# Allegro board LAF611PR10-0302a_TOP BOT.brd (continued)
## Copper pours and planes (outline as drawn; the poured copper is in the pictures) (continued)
LX_3V on BOTTOM (solid shape): 208.01,53.29 209.23,53.29 209.35,53.18 209.35,51.66 209.37,51.64 209.37,51.63 209.45,51.51 209.57,51.43 209.58,51.43 209.94,51.07 210.17,51.07 210.21,51.03 212.29,51.03 212.36,51.1 213.18,51.1 213.25,51.03 213.25,50.86 213.21,50.82 212.39,50.82 212.34,50.77 210.63,50.77 210.22,50.37 209.06,50.37 208.96,50.47 208.61,50.47 208.5,50.36 206.9,50.36 205.66,51.6 203.01,51.6 202.94,51.67 202.94,53.98 203,54.04 207.26,54.04
LX_5V on TOP (solid shape): 123.18,50.74 123.18,49.24 123.1,49.16 121.47,49.16 121.43,49.19 121.43,50.47 121.88,50.91 123.01,50.91
LX_5V on BOTTOM (solid shape): 125.13,53.61 125.13,52.74 124.93,52.55 124.93,52.01 124.37,51.44 124.37,50.71 124.33,50.7 124.19,50.6 124.11,50.43 124.11,50.42 123.56,49.87 123.56,46.75 123.5,46.69 121.13,46.69 121.06,46.76 121.06,50.51 120.28,51.29 120.28,52.07 120.42,52.21 123.65,52.21 124.35,52.91 124.35,53.56 124.49,53.7 125.04,53.7
LX_+1.05V on TOP (solid shape): 140.69,47.28 140.69,46.92 140.5,46.73 139.08,46.73 138.84,46.97 138.84,47.43 139.03,47.63 140.34,47.63
LX_+1.05V on TOP (solid shape): 135.45,46 135.45,44.36 135.36,44.27 134.85,44.27 134.78,44.3 134.75,44.37 134.72,44.51 134.63,44.63 134.63,45.98 134.79,46.13 135.32,46.13
LX_+1.05V on BOTTOM (solid shape): 142.79,51.73 142.79,48.32 142.64,48.17 142.22,48.17 141.21,47.16 141.21,45 141.16,44.95 139.54,44.95 139.48,45.01 139.48,48.16 139.3,48.33 134.9,48.33 134.77,48.46 134.77,51.07 134.89,51.18 139.82,51.18 140.16,51.51 140.16,51.69 140.35,51.88 142.64,51.88
LX_+1.05V on BOTTOM (solid shape): 135.33,45.26 136.15,45.26 136.2,45.22 136.2,44.34 136.16,44.31 135.89,44.31 135.83,44.25 135.58,44.01 135.58,43.99 135.58,43.5 135.51,43.43 135.51,42.67 135.43,42.59 135.28,42.59 135.2,42.67 135.2,43.61 135.2,43.9 134.83,44.27 134.83,45.23 134.99,45.39 135.2,45.39
LX_VCCIO on BOTTOM (solid shape): 52.12,121.6 52.29,121.43 52.29,119.5 52.41,119.38 53.73,119.38 53.85,119.26 53.84,119.24 53.84,117.35 53.17,116.68 51.04,116.68 50.52,116.16 50.52,114.45 50.72,114.25 50.72,113.51 50.56,113.35 49.68,113.35 49.57,113.47 49.57,115.37 48.88,116.06 46.93,116.06 45.83,116.06 45.83,116.22 45.91,116.29 48.55,116.29 48.98,116.72 49.98,116.72 51.23,117.98 51.23,119.43 50.93,119.73 50.93,121.4 51.13,121.61 52.12,121.61
MCT on TOP (solid shape): 18.45,83.09 18.45,75.71 18.85,75.3 18.85,73.27 18.45,72.86 18.45,68.18 18.31,68.04 17.44,68.04 17.3,68.18 17.3,73.39 17.75,73.84 17.75,75.04 17.3,75.49 17.3,83.15 17.52,83.37 18.16,83.37
MCT on BOTTOM (solid shape): 19.43,83.49 19.43,81.72 19.32,81.61 17.74,81.61 17.55,81.79 17.55,83.42 17.64,83.51 19.41,83.51
MIC_CAP on TOP (solid shape): 31.5,22.27 31.5,21.7 31.44,21.64 31.14,21.64 30.86,21.36 30.86,20.3 31.07,20.1 31.07,18.47 31,18.4 30.9,18.4 30.85,18.45 30.85,19.9 30.43,20.32 30.43,22.26 30.47,22.31 31.46,22.31
NVVDD_B+ on TOP (solid shape): 223.71,67.1 223.71,65.41 223.53,65.1 223.71,64.79 223.71,63.25 222.85,62.4 221.65,62.4 221.28,62.77 221.28,67.64 221.54,67.91 222.9,67.91
NVVDD_B+ on TOP (solid shape): 234.07,67.26 234.07,65.54 234.05,65.47 233.98,65.44 233.64,65.09 233.98,64.73 234.05,64.7 234.07,64.63 234.07,62.79 233.55,62.27 233.52,62.27 233.3,62.25 233.14,62.09 231.48,62.09 231.21,62.36 231.21,67.63 231.33,67.75 233.59,67.75
NVVDD_B+ on TOP (solid shape): 214.15,67.34 214.15,65.33 214.09,65.24 213.97,65.27 213.35,65.04 213.97,64.8 214.09,64.83 214.15,64.74 214.15,62.54 213.88,62.26 211.36,62.26 211.16,62.46 211.16,64.12 210.99,64.3 210.99,67.47 211.34,67.82 213.67,67.82
NVVDD_B+ on BOTTOM (solid shape): 225.86,67.81 225.86,66.69 225.74,66.57 224.54,66.57 224.32,66.35 224.32,65.7 224.24,65.62 223.77,65.62 223.49,65.34 223.49,62.29 223.5,62.28 223.5,62.27 224.03,61.75 224.04,61.75 224.22,61.56 230.43,61.56 231.23,62.36 231.23,67.53 231.46,67.77 235.89,67.77 235.93,67.73 235.93,66.54 234.63,66.54 234.43,66.35 234.43,65.59 234.33,65.49 233.83,65.49 233.43,65.08 233.43,62.28 233.39,62.27 233.1,61.92 233.39,61.57 233.43,61.57 233.43,60.71 231.46,58.74 229.13,58.74 229.12,58.76 226,58.76 223.56,56.31 215.82,56.31 215.32,56.81 212.87,56.81 211.18,58.51 211.18,67.43 211.5,67.75 215.87,67.75 215.98,67.64 215.98,66.47 215.85,66.34 214.61,66.34 214.44,66.17 214.44,66.15 214.44,65.49 214.36,65.41 213.53,65.41 213.33,65.21 213.33,62.34 214.12,61.56 215.11,61.56 215.12,61.56 215.23,61.53 215.35,61.56 215.36,61.56 220.14,61.56 221.16,62.57 221.16,67.52 221.52,67.89 225.78,67.89
NVVDD_B+ on VCC: 234.98,62.48 234.9,62.56 218.77,62.56 217.5,63.83 212.24,63.83 212.24,67.64 234.8,67.64 234.98,67.46
PCH_AZ_CODEC_BITCLK on TOP (solid shape): 35.5,15.53 35.5,15.13 35.33,14.96 35.33,14.35 35.26,14.27 34.8,14.27 34.72,14.35 34.72,15.7 34.42,16 32.92,16 32.84,16.08 32.84,16.18 32.89,16.23 34.8,16.23
RING2 on TOP (solid shape): 17.17,14.6 17.17,12.01 17.09,11.94 16.61,11.94 16.54,12.01 16.54,14.55 16.66,14.68 17.09,14.68
RING2 on TOP (solid shape): 32.66,20.53 32.66,20.35 31.87,19.56 31.87,18.45 31.85,18.42 31.69,18.42 31.62,18.5 31.62,20.48 31.8,20.66 32.53,20.66
RING2_R on TOP (solid shape): 17.14,11.51 17.14,8.79 16.68,8.32 15.77,8.32 15.27,8.82 15.27,10.4 15.51,10.65 15.51,11.52 15.62,11.63 17.03,11.63
SA_SW on BOTTOM (solid shape): 103.42,139.01 103.42,138.24 103.37,138.2 102.1,138.2 101.95,138.05 101.95,134.27 101.87,134.19 101.1,134.19 101.1,134.18 99.88,135.4 99.88,136.57 99.72,136.73 99.63,136.73 99.63,136.73 99.52,136.75 99.41,136.73 99.4,136.73 98.39,136.73 98.39,137.63 98.36,137.66 97.63,137.66 97.59,137.62 97.59,136.76 97.56,136.73 96.6,136.73 96.54,136.78 96.54,138.88 96.69,139.02 103.41,139.02
SLEEVE on TOP (solid shape): 18.6,14.43 18.6,13.68 18.52,13.61 18.37,13.61 18.16,13.4 18.16,11.99 18.11,11.94 17.54,11.94 17.5,11.98 17.5,14.34 17.72,14.56 18.47,14.56
SLEEVE on TOP (solid shape): 32.07,21.28 32.1,21.23 32.12,21.19 32.12,20.98 31.98,20.84 31.78,20.84 31.47,20.52 31.47,18.45 31.41,18.4 31.3,18.4 31.23,18.47 31.23,20.24 31.01,20.46 31.01,21.28 31.22,21.49 31.75,21.49 31.85,21.5
SLEEVE_R on TOP (solid shape): 19.13,11.54 19.13,10.77 19.46,10.44 19.46,8.93 19.14,8.62 17.73,8.62 17.47,8.88 17.47,11.53 17.55,11.61 19.06,11.61
SNB_1.0VS_VGAP on BOTTOM (solid shape): 201.49,78.38 201.49,77.34 201.09,76.94 201.09,76.38 200.98,76.28 200.44,76.28 200.29,76.43 200.29,78.29 200.47,78.47 201.4,78.47
SNB_VCCIO on BOTTOM (solid shape): 54.45,121.47 54.53,121.44 54.61,121.44 54.7,121.44 54.79,121.47 54.98,121.47 55.11,121.34 55.11,120.89 55.19,120.81 55.64,120.81 55.74,120.71 55.74,119.73 55.66,119.65 53.69,119.65 53.55,119.79 53.55,121.41 53.62,121.47 54.44,121.47
SNUB1_CHG on TOP (solid shape): 243.8,45.02 243.8,42.48 243.73,42.4 242.9,42.4 242.75,42.56 242.75,43.56 242.49,43.81 241.99,43.81 241.81,43.99 241.81,44.98 241.92,45.1 243.73,45.1
SNUB2_CHG on TOP (solid shape): 240.93,56.28 240.93,55.08 240.67,54.83 237.63,54.83 237.44,55.02 237.44,56.22 237.66,56.44 240.77,56.44
SNUB_+1.05V on BOTTOM (solid shape): 141.34,43.43 141.34,42.44 141.18,42.29 140.7,42.29 140.36,41.95 140.36,41.45 140.21,41.3 139.58,41.3 139.43,41.45 139.43,43.41 139.53,43.51 141.26,43.51
TBT_SVR_IND on BOTTOM (solid shape): 17.98,135.95 17.98,134.97 18.56,134.38 19.26,134.38 20.46,133.18 20.46,133 20.71,132.75 20.96,132.75 21.05,132.66 21.05,132.42 20.99,132.36 20.78,132.36 20.63,132.21 20.63,132 20.56,131.94 20.44,131.94 20.37,132.01 20.37,132.65 19.83,133.19 18.17,133.19 17.26,132.28 15.77,132.28 15.53,132.52 15.53,136.05 15.74,136.26 17.66,136.26
UG1_CHG on TOP (solid shape): 246.77,51.92 246.77,50.35 246.52,50.1 245.66,50.1 245.45,50.3 245.45,51.91 245.65,52.11 246.58,52.11
UG1_CHG on TOP (solid shape): 250.77,37.51 250.77,36.74 250.95,36.57 250.95,35.67 250.73,35.45 249.95,35.45 249.85,35.56 249.85,36.37 249.64,36.58 249.64,37.54 249.79,37.69 250.59,37.69
UG1_CHG on TOP (solid shape): 266.45,51.74 266.45,50.93 266.5,50.89 266.5,50.44 266.07,50.01 265.61,50.01 265.48,50.14 265.48,50.34 265.66,50.52 265.86,50.52 266.22,50.87 266.22,51.74 266.27,51.79 266.4,51.79
UG1_CHG on BOTTOM (solid shape): 247.04,51.79 247.04,51.23 246.77,50.96 245.66,50.96 245.54,51.09 245.54,51.93 245.7,52.09 246.74,52.09
UG1_CHG on BOTTOM (solid shape): 251.1,36.98 251.1,35.66 250.98,35.53 250.27,35.53 250.04,35.76 250.04,37.06 250.27,37.29 250.8,37.29
UG2_CHG on TOP (solid shape): 242.89,50.86 242.89,49.9 242.72,49.73 241.66,49.73 241.39,50 241.39,50.93 241.49,51.03 242.72,51.03
UG2_CHG on TOP (solid shape): 265.24,53.34 265.24,53.24 265.16,53.16 264.23,53.16 264,52.94 263.16,52.94 262.99,53.11 262.99,53.27 263.14,53.41 265.17,53.41
UG2_CHG on BOTTOM (solid shape): 235.41,50.83 235.41,50.47 234.93,49.98 234.53,49.98 234.16,50.36 234.16,51.32 234.16,51.34 234.3,51.48 234.76,51.48
UG_1.2V on TOP (solid shape): 37.87,46.15 37.87,45.07 37.61,44.81 36.69,44.81 36.57,44.94 36.57,46.11 36.81,46.35 37.66,46.35
UG_1.2V on TOP (solid shape): 38.37,51.17 38.37,49.77 38.28,49.68 37.66,49.68 37.51,49.82 37.51,51.52 37.64,51.65 37.9,51.65
UG_1.2V on BOTTOM (solid shape): 37.08,45.88 37.08,45.35 37.08,45.34 37.08,44.83 37.06,44.81 37.06,43.98 37,43.91 36.89,43.91 36.84,43.97 36.84,44.77 36.53,45.08 36.53,45.81 36.73,46.01 36.95,46.01
UG_1.2V on BOTTOM (solid shape): 38.23,51.34 38.23,50.94 38.54,50.64 38.54,50.62 38.76,50.4 38.76,49.92 38.68,49.84 37.99,49.84 37.88,49.95 37.88,50.44 37.53,50.79 37.53,51.54 37.64,51.65 37.92,51.65
UG_+1.05V on TOP (solid shape): 136.03,52.43 136.03,51.77 135.85,51.59 135.39,51.59 134.45,52.52 134.45,52.79 134.65,52.98 135.48,52.98
UG_+1.05V on TOP (solid shape): 137.08,44.93 137.08,43.98 136.95,43.85 135.77,43.85 135.71,43.91 135.71,44.88 135.9,45.07 136.94,45.07
UG_+1.05V on BOTTOM (solid shape): 135.59,53.39 135.59,52.58 135.43,52.42 134.65,52.42 134.47,52.6 134.47,53.46 134.82,53.81 135.17,53.81
UG_+1.05V on BOTTOM (solid shape): 136.87,44.05 136.87,43.79 136.72,43.64 136.25,43.64 136,43.39 136,42.66 135.92,42.58 135.8,42.58 135.7,42.68 135.7,43.44 135.71,43.46 135.71,43.96 135.88,44.12 135.88,44.12 135.94,44.18 136.75,44.18
USB20_VCCB on TOP (solid shape): 269.55,35.32 269.55,34.07 269.19,33.71 269.19,31.38 268.9,31.09 267.58,31.09 266.88,31.79 266.88,35.37 267.24,35.73 269.15,35.73
USB20_VCCB on BOTTOM (solid shape): 270.33,34.9 270.33,32.6 270.19,32.46 266.81,32.46 266.62,32.65 266.62,35.94 266.73,36.04 269.19,36.04
USB30_VCCA on TOP (solid shape): 18.43,59.21 18.43,56.54 18.17,56.29 15.74,56.29 15.52,56.5 15.52,59.12 15.96,59.56 18.08,59.56
USB30_VCCA on TOP (solid shape): 18.62,39.1 18.62,35.48 18.86,35.24 19.24,35.24 19.31,35.22 19.34,35.15 19.56,34.85 19.93,34.9 19.99,34.93 20.28,34.82 20.57,34.93 20.87,34.82 21.16,34.93 21.22,34.9 21.59,34.85 21.81,35.15 21.84,35.21 21.91,35.24 22,35.24 22.25,35.49 22.25,37.05 22.37,37.16 23.98,37.16 24.29,36.85 24.29,36.3 24.08,36.09 23.57,36.09 23.34,35.85 23.34,34.5 22.81,33.98 22.81,33.4 22.56,33.14 22.56,31.7 22.41,31.55 22.14,31.55 21.43,32.26 21.33,32.26 21.33,33.16 21.09,33.4 19.77,33.4 18.94,32.56 17.68,32.56 17.28,32.16 17.21,32.16 17.15,32.11 15.65,32.11 15.22,32.54 15.22,36.42 15.72,36.93 16.82,36.93 16.82,39.43 18.29,39.43
USB30_VCCA on BOTTOM (solid shape): 19.41,39.19 19.41,37.37 19.28,37.23 19.11,37.23 18.8,36.93 17.45,36.93 17.17,37.2 17.17,39.09 17.46,39.38 19.22,39.38
USB30_VCCA on BOTTOM (solid shape): 20.17,62.33 20.17,57.33 20.03,57.19 19.1,57.19 17.9,55.99 15.61,55.99 15.23,56.37 15.23,59.24 15.4,59.41 15.4,62.05 16.1,62.75 19.75,62.75
USBC_B2B_S1 on BOTTOM (solid shape): 33.77,46.94 33.77,46.35 33.18,45.77 32.63,45.77 32.37,45.51 32.35,45.51 32.29,45.45 32.27,45.45 32.04,45.34 31.94,45.1 31.94,45.08 31.92,45.06 31.92,44.84 31.23,44.15 31.23,42.84 31.15,42.77 28.82,42.77 28.81,42.77 28.65,42.81 28.49,42.77 28.48,42.77 28.33,42.77 28.06,42.89 27.79,42.77 27.61,42.77 27.61,42.77 27.48,42.79 27.36,42.77 27.35,42.77 27.07,42.77 27.03,42.8 27.03,44.11 27.06,44.14 29.42,44.14 29.6,44.14 30.72,45.27 31.29,45.27 32.07,46.05 32.29,46.05 32.67,46.43 32.67,46.93 32.85,47.11 33.6,47.11
USBC_B2B_S2_G on BOTTOM (solid shape): 26.45,43.26 26.45,42.32 26.34,42.22 26.13,42.22 25.99,42.35 25.99,42.8 25.86,42.93 25.14,42.93 24.96,42.74 24.95,42.74 24.95,42.25 24.89,42.19 24.3,42.19 23.46,41.36 22.51,41.36 22.15,41.71 22.15,42.49 23.29,43.64 26.08,43.64
VBST_+1.05V on BOTTOM (solid shape): 138.96,43.38 138.96,42.72 138.84,42.59 136.27,42.59 136.2,42.67 136.2,43.38 136.32,43.51 138.84,43.51
VGA_SW1 on BOTTOM (solid shape): 213.24,73.74 214,73.74 214,74.65 215.7,74.65 216.64,73.71 216.64,73.69 216.74,73.47 216.96,73.37 216.98,73.37 218.86,71.49 218.86,68.86 218.83,68.83 218.13,68.83 218.12,68.84 218.12,70.15 217.92,70.35 214.1,70.35 214.08,70.38 214.08,70.73 212.64,72.17 211.88,72.17 211.76,72.29 211.76,74.65 213.24,74.65
VGA_SW2 on BOTTOM (solid shape): 223.99,73.91 224.76,73.91 224.76,74.81 228.33,74.81 228.7,74.44 228.7,74.21 228.65,74.12 228.55,74.12 228.01,73.82 228.55,73.51 228.65,73.52 228.7,73.43 228.7,69.04 228,69.04 228,69.05 228,70.34 227.8,70.53 224,70.53 223.99,70.54 223.99,71.06 222.61,72.44 222.61,74.81 222.62,74.81 223.99,74.81
VGA_SW3 on BOTTOM (solid shape): 234.6,74.77 234.67,74.7 234.67,73.76 234.74,73.69 235.43,73.69 235.48,73.74 235.48,74.57 235.69,74.78 236.85,74.78 237.92,73.71 237.92,71.93 238.89,70.96 238.89,68.99 238.81,68.91 238.04,68.91 237.96,68.99 237.96,70.1 237.73,70.33 234.16,70.33 233.3,71.2 233.3,74.61 233.48,74.79 234.6,74.79
N12281337 on TOP (solid shape): 36.27,19.54 36.27,19.03 36.15,18.91 35.53,18.91 35.01,18.39 34.14,18.39 34.11,18.36 34.11,18.36 33.76,18.01 32.91,18.01 32.86,18.06 32.86,18.25 33.6,18.98 34.74,18.98 35.33,19.57 36.24,19.57
N16946088 on BOTTOM (solid shape): 200.57,89.86 200.57,88.93 200.52,88.87 199.81,88.87 199.76,88.93 199.76,89.43 199.62,89.57 198.99,89.57 198.86,89.7 198.86,90.14 199.01,90.29 200.14,90.29
N17283936 on TOP (solid shape): 39.61,24.05 39.61,22.64 39.1,22.13 39.1,21.58 39.07,21.54 37.86,21.54 37.81,21.59 37.81,22.12 38.38,22.69 38.38,23.87 38.85,24.34 39.32,24.34
N17389450 on BOTTOM (solid shape): 130.85,59.21 130.85,58.4 130.76,58.31 130.15,58.31 129.85,58.01 129.85,55.59 129.77,55.5 129.22,55.5 129.08,55.64 129.08,56.15 128.95,56.28 128.43,56.28 128.28,56.43 128.28,57.13 128.39,57.24 128.66,57.24 128.85,57.43 128.86,57.43 128.88,57.45 128.94,57.45 128.94,57.51 129.02,57.59 129.02,57.6 129.21,57.79 129.21,59.07 129.26,59.11 129.34,59.22 129.37,59.36 129.38,59.37 130.69,59.37
N19136586 on TOP (solid shape): 274.35,42.89 274.35,41.49 274.22,41.36 273.33,41.36 273.2,41.49 273.2,43.01 273.33,43.14 274.09,43.14
N20816750 on BOTTOM (solid shape): 59.87,151.66 59.87,151.08 59.82,151.03 59.46,151.03 59.02,150.58 58.71,150.58 58.54,150.41 58.54,149.79 58.48,149.73 58.24,149.73 58.19,149.78 58.19,150.53 58.53,150.87 58.72,150.87 58.9,151.05 58.9,151.69 58.93,151.71 59.82,151.71
N20816752 on BOTTOM (solid shape): 61.06,151.69 61.06,151.07 60.6,150.61 59.76,150.61 59.54,150.39 59.54,149.81 59.46,149.73 59.26,149.73 59.2,149.79 59.2,150.5 59.53,150.82 59.6,150.9 59.87,150.9 59.88,150.91 59.92,150.91 60.07,151.05 60.07,151.64 60.15,151.71 61.04,151.71
N20816771 on BOTTOM (solid shape): 61.09,153.07 61.09,152.51 61.03,152.46 58.93,152.46 58.85,152.53 58.85,153.1 58.9,153.15 61.01,153.15
N20816775 on BOTTOM (solid shape): 57.73,151.69 58.59,151.69 58.65,151.64 58.65,151.1 58.57,151.03 57.73,151.03 57.53,150.82 57.53,149.78 57.48,149.73 57.28,149.73 57.2,149.81 57.2,150.7 56.79,151.11 56.67,151.11 56.66,151.12 56.66,152.01 56.69,152.04 57.38,152.04
N20816821 on BOTTOM (solid shape): 107.25,134.79 107.25,134.42 107.44,134.23 108.02,134.23 108.07,134.18 108.07,133.28 108.04,133.26 107.29,133.26 106.95,133.6 106.95,134.61 106.78,134.78 106.19,134.78 106.09,134.88 106.09,135.02 106.18,135.11 106.93,135.11
N20816822 on BOTTOM (solid shape): 107.24,135.95 107.24,135.61 107.41,135.45 108.04,135.45 108.07,135.42 108.07,134.5 108.04,134.47 107.43,134.47 107.38,134.52 107.38,134.94 106.95,135.37 106.95,135.6 106.77,135.78 106.18,135.78 106.09,135.88 106.09,136.01 106.19,136.11 107.09,136.11
N20816832 on BOTTOM (solid shape): 108.38,137.52 108.38,136.82 108.06,136.5 108.06,135.84 108.05,135.83 108.05,135.68 108.03,135.66 107.42,135.66 107.38,135.7 107.38,136.46 107.05,136.79 106.18,136.79 106.09,136.88 106.09,137.01 106.18,137.1 107.05,137.1 107.4,137.45 107.4,137.51 107.44,137.55 108.35,137.55
N20816859 on BOTTOM (solid shape): 109.5,135.41 109.5,133.3 109.43,133.23 108.87,133.23 108.81,133.28 108.81,135.38 108.89,135.46 109.45,135.46
N21379353 on BOTTOM (solid shape): 126.46,53.61 126.46,53.16 127.3,52.32 129.69,52.32 129.78,52.22 130.69,52.22 130.83,52.09 130.83,51.3 130.71,51.18 127.04,51.18 125.81,52.41 125.81,52.75 125.73,52.83 125.73,53.59 125.82,53.68 126.38,53.68
N21449588 on TOP (solid shape): 52.06,141.21 52.73,141.21 52.86,141.08 52.86,141.04 52.86,140.41 52.73,140.28 50.19,140.28 50.06,140.41 50.06,141.3 50.19,141.43 51.84,141.43
N21449609 on TOP (solid shape): 55.02,139.49 55.02,137.13 54.79,136.89 53.66,136.89 53.52,137.03 53.52,138.29 53.12,138.68 53.12,139.52 53.25,139.65 54.86,139.65
N21484822 on TOP (solid shape): 198.79,69.97 198.79,69.6 198.52,69.33 198.52,67.74 198.22,67.43 198.18,67.47 197.76,67.54 197.57,67.16 197.55,67.08 197.47,67.04 195.99,67.04 195.95,67.08 195.95,67.5 195.96,67.53 196,67.55 196.32,67.9 196,68.26 195.96,68.27 195.95,68.31 195.95,69.47 196.53,70.04 198.72,70.04
N21484822 on BOTTOM (solid shape): 199.21,69.76 199.21,67.69 199.13,67.6 197.75,67.6 197.51,67.36 197.51,66.78 197.33,66.6 196.45,66.6 196.33,66.72 196.33,69.67 196.86,70.19 198.78,70.19
N21741739 on TOP (solid shape): 22.05,54.25 22.05,53.47 21.95,53.37 21.15,53.37 20.98,53.54 20.98,54.24 21.14,54.4 21.9,54.4
N21741739 on TOP (solid shape): 26.57,54.3 26.57,53.54 26.44,53.41 25.68,53.41 25.55,53.54 25.55,54.3 25.68,54.43 26.44,54.43
N25756286 on TOP (solid shape): 24.63,56.22 24.63,55.46 24.49,55.32 23.65,55.32 23.59,55.38 23.59,56.27 23.68,56.37 24.48,56.37
N25756286 on TOP (solid shape): 29.24,56.08 29.24,55.58 28.98,55.32 28.22,55.32 28.09,55.45 28.09,56.21 28.22,56.34 28.98,56.34
N26877609 on BOTTOM (solid shape): 214.94,66.08 214.94,65.29 214.59,64.94 214.59,64.07 214.47,63.94 213.57,63.94 213.47,64.05 213.47,65.11 213.63,65.27 214.41,65.27 214.62,65.49 214.62,66.08 214.71,66.17 214.86,66.17
N26877615 on BOTTOM (solid shape): 215.95,66.08 215.95,65.19 215.75,65 215.75,64.1 215.64,63.99 214.8,63.99 214.72,64.07 214.72,64.85 215.03,65.16 215.04,65.16 215.17,65.29 215.42,65.29 215.62,65.5 215.62,66.06 215.72,66.15 215.87,66.15
N26877657 on BOTTOM (solid shape): 216.94,66.07 216.94,64.96 217.18,64.72 218.1,64.72 218.11,64.71 218.11,64.03 218.04,63.96 216.11,63.96 215.98,64.09 215.98,64.85 216.62,65.48 216.62,66.06 216.72,66.16 216.85,66.16
N26877691 on BOTTOM (solid shape): 225.83,66.27 225.83,65.64 225.87,65.6 225.87,63.96 225.74,63.84 224.93,63.84 224.85,63.92 224.85,64.58 225,64.73 225,65.08 224.99,65.09 224.99,65.22 225.5,65.73 225.5,66.27 225.59,66.36 225.73,66.36
N26877733 on BOTTOM (solid shape): 215.75,63.33 215.75,62.43 215.66,62.34 213.61,62.34 213.46,62.49 213.46,63.32 213.58,63.44 215.64,63.44
N26877795 on BOTTOM (solid shape): 224.83,66.27 224.83,64.92 224.68,64.77 224.68,63.88 224.6,63.8 223.74,63.8 223.64,63.9 223.64,65.24 223.85,65.45 224.32,65.45 224.5,65.63 224.5,66.27 224.59,66.36 224.74,66.36
N26877907 on BOTTOM (solid shape): 226.82,66.27 226.82,65.62 226.85,65.59 226.85,64.82 227.1,64.57 228.14,64.57 228.2,64.51 228.2,63.88 228.01,63.7 226.22,63.7 226.02,63.89 226.02,65.23 226.47,65.67 226.49,65.69 226.49,66.26 226.59,66.36 226.73,66.36
N26878499 on BOTTOM (solid shape): 235.93,66.16 235.93,64.05 235.86,63.98 234.94,63.98 234.87,64.05 234.87,65.05 235.12,65.29 235.31,65.29 235.58,65.56 235.58,66.15 235.67,66.25 235.84,66.25
N26878505 on BOTTOM (solid shape): 234.82,66.24 234.9,66.15 234.9,65.3 234.64,65.04 234.64,64.05 234.61,64.01 233.7,64.01 233.65,64.06 233.65,65.09 233.91,65.35 234.39,65.35 234.56,65.52 234.56,66.13 234.67,66.24
N26878545 on BOTTOM (solid shape): 235.88,63.25 235.88,62.52 235.66,62.3 233.95,62.3 233.65,62.6 233.65,63.24 233.8,63.39 235.74,63.39
N26893128 on BOTTOM (solid shape): 225.8,63.39 225.8,62.08 225.59,61.87 224.08,61.87 223.63,62.32 223.63,63.33 223.8,63.5 225.69,63.5
N26894100 on BOTTOM (solid shape): 236.93,66.12 236.93,64.91 237.15,64.68 238.23,64.68 238.27,64.65 238.27,64 238.26,63.99 236.14,63.99 236.05,64.07 236.05,64.85 236.56,65.36 236.56,66.14 236.66,66.24 236.81,66.24
N27238858 on TOP (solid shape): 91.97,140.23 91.97,139.29 92.13,139.14 93.14,139.14 93.22,139.06 93.22,138.33 93.14,138.25 91.01,138.25 90.88,138.38 90.88,140.21 90.96,140.28 91.92,140.28
N27238942 on TOP (solid shape): 83.57,146.2 83.57,145.26 83.8,145.03 84.81,145.03 84.89,144.96 84.89,144.4 84.84,144.35 82.58,144.35 82.37,144.55 82.37,146.18 82.47,146.28 83.49,146.28
N27239057 on TOP (solid shape): 75.26,146.28 75.26,145.63 75.65,145.24 76.48,145.24 76.58,145.13 76.58,144.45 76.53,144.4 74.24,144.4 74.14,144.5 74.14,146.3 74.17,146.33 75.21,146.33
N27239175 on TOP (solid shape): 67.11,146.2 67.11,145.26 67.31,145.06 68.3,145.06 68.43,144.93 68.43,144.4 68.33,144.3 66.14,144.3 65.91,144.52 65.91,146.2 66.02,146.3 67.01,146.3
N27239423 on TOP (solid shape): 58.8,145.13 58.8,144.32 58.98,144.14 59.97,144.14 60.1,144.02 60.1,143.43 60.02,143.36 57.73,143.36 57.68,143.41 57.68,145.13 57.76,145.21 58.73,145.21
N27239504 on TOP (solid shape): 101.86,135.97 101.86,135.01 101.8,134.94 101.2,134.94 100.76,134.51 100.76,133.72 100.7,133.66 100.08,133.66 100.03,133.71 100.03,135.97 100.12,136.07 101.76,136.07
N27327907 on TOP (solid shape): 35.85,58.16 35.85,57.62 35.98,57.48 35.98,55.49 35.65,55.15 34.85,55.15 34.45,55.55 34.45,58.15 34.54,58.23 35.77,58.23
N27484470 on BOTTOM (solid shape): 267.26,71.5 267.26,71.02 265.43,69.19 265.43,69.14 265.38,69.09 265.28,69.09 265.23,69.14 265.23,69.9 265.81,70.48 265.81,70.6 265.81,70.61 265.81,71.5 265.86,71.55 267.21,71.55
N27933518 on BOTTOM (solid shape): 69.32,152.45 69.32,151.69 68.89,151.26 68.32,151.26 68.04,151.34 67.85,151.12 67.84,151.11 67.79,151.06 67.79,150.57 67.72,150.5 67.51,150.5 67.46,150.55 67.46,151.13 67.92,151.59 68.1,151.59 68.33,151.82 68.33,152.4 68.4,152.48 69.29,152.48
N27933520 on BOTTOM (solid shape): 68.12,152.43 68.12,151.84 68.07,151.79 67.72,151.79 67.28,151.36 66.98,151.36 66.79,151.17 66.79,150.55 66.73,150.5 66.5,150.5 66.45,150.55 66.45,151.3 66.79,151.64 66.98,151.64 67.16,151.82 67.16,152.45 67.18,152.48 68.07,152.48
N27933540 on BOTTOM (solid shape): 65.99,152.46 66.85,152.46 66.9,152.4 66.9,151.87 66.83,151.79 65.99,151.79 65.79,151.59 65.79,150.55 65.74,150.5 65.53,150.5 65.46,150.57 65.46,151.46 65.04,151.88 64.92,151.88 64.91,151.89 64.91,152.26 64.92,152.32 64.91,152.39 64.91,152.77 64.95,152.81 65.64,152.81
N27933602 on BOTTOM (solid shape): 69.34,153.84 69.34,153.28 69.29,153.22 67.18,153.22 67.11,153.3 67.11,153.86 67.16,153.91 69.27,153.91
N28761690 on BOTTOM (solid shape): 229.08,48.4 229.08,48.15 228.87,47.94 228.87,47.34 228.24,46.71 227.92,46.71 227.77,46.86 227.77,47.45 228.05,47.73 228.05,48.37 228.19,48.51 228.97,48.51
N28769298 on TOP (solid shape): 234.85,54.57 235.4,54.57 235.4,54.07 234.85,54.07 234.85,53.37 235.4,53.37 235.4,52.87 234.86,52.87 234.85,52.87 234.83,52.84 234.83,51.65 234.25,51.07 234.25,48.06 234.18,47.99 234.18,43.43 233.73,42.98 229.76,42.98 229.63,43.12 229.63,44.61 229.57,44.61 229.57,44.62 229.05,44.62 229.05,45.06 229.57,45.06 229.57,45.82 229.05,45.82 229.05,46.26 229.57,46.26 229.57,46.27 229.63,46.27 229.63,50.61 229.9,50.87 229.9,52.26 229.63,52.53 229.63,52.71 229.66,52.78 229.73,52.81 230.09,53.17 229.73,53.53 229.66,53.56 229.63,53.63 229.63,54.98 229.99,55.35 234.85,55.35
N28769298 on BOTTOM (solid shape): 236.13,55.08 236.13,51.01 235.65,51.01 235.64,51.03 235.64,51.97 233.63,51.97 233.1,51.43 233.1,47.85 232.2,46.95 232.2,40.08 232.04,39.91 230.64,39.91 230.49,40.05 230.49,40.61 231.06,40.61 231.42,40.97 231.06,41.33 230.49,41.33 230.49,41.8 229.6,42.7 229.6,43.84 229.59,43.84 229.05,43.84 229.05,43.84 229.05,44.29 229.05,44.3 229.58,44.3 229.6,44.31 229.6,45.04 229.59,45.04 229.05,45.04 229.05,45.05 229.05,45.49 229.05,45.5 229.58,45.5 229.6,45.52 229.6,46.29 229.25,46.64 229.25,48.49 229,48.75 228.16,48.75 228.07,48.84 228.07,50.43 228.07,50.43 228.07,50.7 229.64,52.27 229.64,52.8 229.67,52.81 229.71,52.81 230.09,53.17 229.71,53.53 229.67,53.53 229.64,53.54 229.64,54.77 230.12,55.25 235.96,55.25
N28866414 on TOP (solid shape): 275.23,51.26 275.23,46.63 274.93,46.33 272.52,46.33 272.44,46.4 272.44,48.13 272.06,48.51 272.06,49.27 272.19,49.4 273.51,49.4 273.61,49.4 274.07,49.86 274.07,51.31 274.07,51.31 274.19,51.36 274.28,51.43 275.06,51.43
N28866597 on TOP (solid shape): 260.04,52.41 260.04,50.35 259.9,50.21 259.2,50.21 259.08,50.33 259.08,52.4 259.23,52.56 259.9,52.56
N32320644 on TOP (solid shape): 266.85,69.79 267.02,69.59 267.28,69.57 267.31,69.58 267.45,69.44 267.45,68.87 266.78,68.2 266.33,68.2 266.24,68.29 266.24,69.73 266.32,69.82 266.84,69.82
N32320644 on BOTTOM (solid shape): 268.12,69.3 268.12,68.79 268.09,68.75 267.25,68.75 266.74,68.24 265.71,68.24 265.63,68.32 265.63,68.42 265.69,68.48 266.46,68.48 266.56,68.58 266.59,68.61 266.61,68.64 267.33,69.35 268.07,69.35
N32320879 on BOTTOM (solid shape): 265.05,66.83 265.05,65.58 264.69,65.21 264.69,64.79 264.62,64.73 264.07,64.73 264.03,64.76 264.03,65.32 264.07,65.36 264.21,65.36 264.82,65.97 264.82,66.83 264.87,66.88 265,66.88
N32320932 on BOTTOM (solid shape): 268.11,68.5 268.11,67.93 268.04,67.86 265.7,67.86 265.63,67.93 265.63,68.01 265.7,68.09 266.85,68.09 267.29,68.52 268.09,68.52
N32321023 on BOTTOM (solid shape): 264.74,81.05 264.74,80.06 264.67,79.98 263.91,79.98 263.7,79.78 263.7,78.99 263.58,78.87 263.04,78.87 262.92,78.99 262.92,81.08 262.97,81.13 264.67,81.13
N32321094 on BOTTOM (solid shape): 269.05,71.07 269.05,67.96 268.99,67.91 268.52,67.91 268.47,67.96 268.47,71.03 268.55,71.12 269,71.12
N32332705 on BOTTOM (solid shape): 268.11,70.15 268.11,69.62 268.06,69.57 267.36,69.57 267.03,69.24 266.97,69.18 266.91,69.12 266.46,68.67 265.69,68.67 265.64,68.72 265.64,68.83 267.02,70.2 268.06,70.2
N40598435 on BOTTOM (solid shape): 210.57,54.63 210.57,54.02 210.52,53.97 209.73,53.97 209.32,53.57 208.71,53.57 208.66,53.62 208.66,54.23 209.14,54.71 210.49,54.71
N40598619 on BOTTOM (solid shape): 133.23,59.22 133.23,57.51 133.04,57.32 132.31,57.32 132.28,57.35 132.28,58.23 132.2,58.3 131.78,58.3 131.7,58.38 131.7,59.29 131.78,59.37 133.08,59.37
N42077965 on BOTTOM (solid shape): 94.91,146.58 94.91,145.81 94.82,145.72 94.45,145.72 94.06,145.33 92.91,145.33 92.7,145.11 92.7,144.58 92.62,144.5 92.43,144.5 92.33,144.59 92.33,145.32 92.54,145.52 93.55,145.52 93.77,145.74 93.77,146.56 93.89,146.68 94.82,146.68
N42077969 on BOTTOM (solid shape): 91.69,146.38 91.69,144.58 91.6,144.49 91.45,144.49 91.37,144.56 91.37,145.34 91.01,145.71 90.48,145.71 90.43,145.76 90.43,146.67 90.47,146.71 91.35,146.71
N42078041 on BOTTOM (solid shape): 85.83,152.45 85.83,151.69 85.4,151.26 84.83,151.26 84.55,151.34 84.36,151.12 84.35,151.11 84.3,151.06 84.3,150.57 84.23,150.5 84.02,150.5 83.97,150.55 83.97,151.13 84.43,151.59 84.61,151.59 84.84,151.82 84.84,152.4 84.91,152.48 85.8,152.48
N42078055 on BOTTOM (solid shape): 84.63,152.43 84.63,151.84 84.58,151.79 84.23,151.79 83.75,151.32 83.72,151.33 83.5,151.31 83.36,151.13 83.36,151.12 83.3,151.07 83.3,150.55 83.24,150.5 83.01,150.5 82.96,150.55 82.96,151.3 83.3,151.64 83.49,151.64 83.67,151.82 83.67,152.45 83.69,152.48 84.58,152.48
N42078421 on BOTTOM (solid shape): 92.56,146.66 93.41,146.66 93.46,146.6 93.46,145.79 93.39,145.72 91.88,145.72 91.82,145.79 91.82,146.43 91.81,146.44 91.81,146.66 91.87,146.73 92.49,146.73
N42078657 on BOTTOM (solid shape): 85.85,153.84 85.85,153.28 85.8,153.22 83.69,153.22 83.62,153.3 83.62,153.86 83.67,153.91 85.78,153.91
N42078671 on BOTTOM (solid shape): 82.48,152.49 83.36,152.49 83.41,152.43 83.41,151.87 83.34,151.79 82.5,151.79 82.3,151.59 82.3,150.55 82.25,150.5 82.04,150.5 81.97,150.57 81.97,151.48 81.56,151.88 81.47,151.88 81.45,151.9 81.45,152.26 81.46,152.33 81.45,152.41 81.45,152.78 81.47,152.81 82.16,152.81
N42079748 on BOTTOM (solid shape): 76.38,152.43 76.38,151.84 76.33,151.79 75.97,151.79 75.5,151.32 75.47,151.33 75.24,151.31 75.1,151.13 75.1,151.12 75.05,151.07 75.05,150.55 74.99,150.5 74.75,150.5 74.7,150.55 74.7,151.3 75.04,151.64 75.23,151.64 75.41,151.82 75.41,152.45 75.44,152.48 76.33,152.48
N42079752 on BOTTOM (solid shape): 77.57,152.45 77.57,151.69 77.23,151.35 76.4,151.35 76.35,151.35 76.26,151.35 76.22,151.31 76.2,151.31 76.05,151.15 76.05,150.57 75.97,150.5 75.8,150.5 75.72,150.58 75.72,151.28 76.1,151.66 76.42,151.66 76.58,151.82 76.58,152.4 76.66,152.48 77.55,152.48
N42079902 on BOTTOM (solid shape): 77.6,153.84 77.6,153.28 77.54,153.22 75.44,153.22 75.36,153.3 75.36,153.86 75.41,153.91 77.52,153.91
N42079910 on BOTTOM (solid shape): 74.2,152.5 75.1,152.5 75.13,152.47 75.13,151.84 75.08,151.79 74.55,151.79 74.04,151.28 74.04,150.55 73.99,150.5 73.79,150.5 73.71,150.57 73.71,151.29 73.66,151.34 73.66,151.39 73.49,151.56 73.48,151.57 73.4,151.75 73.23,151.86 73.19,151.87 73.19,152.71 73.28,152.81 73.9,152.81
N47714748 on TOP (solid shape): 37.74,53.46 37.74,51.87 37.67,51.79 35.81,51.79 35.76,51.84 35.76,52.83 36.55,53.62 37.59,53.62
N47719295 on BOTTOM (solid shape): 34.17,44.69 34.17,43.27 34.75,42.68 34.75,42.57 34.67,42.49 33.58,42.49 33.47,42.6 33.47,44.68 33.52,44.73 34.13,44.73
N47887852 on BOTTOM (solid shape): 207,71.25 207,70.66 206.95,70.61 206.68,70.61 206,69.93 205.12,69.93 205.02,70.03 205.02,71.68 205.1,71.76 206.49,71.76

Small or netless copper shapes (teardrops, artwork), in the pictures only: 136 on TOP, 43 on BOTTOM

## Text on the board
Ref Des/Silkscreen Bottom: H2 | A | H7 | H5
User.Comments: PJPM04 | CR_UNNAMED_1 | CR_UNNAMED_6 | CR_UNNAMED_7 | CR_UNNAMED_8 | CR_UNNAMED_9 | CR_UNNAMED_10 | LA-F611P | 2018-03-02 | 2019-03-02 | CAL53 | Milly | +DC_IN
Ref Des/Silkscreen Top: HF
BODY_CENTER: LAYER | NO. | L1 | L2 | L3 | L4 | L5 | L6 | L7 | L8 | L9 | L10 | LA-F611P | GND2 | TOP | GND1 | IN2 | IN3 | GND3 | IN4 | VCC | IN1 | BOT
User.37: LAYER | NAME | STACKUP: 10 LAYER | 39 ohm | 5.6mil | 6.6mil | 50 ohm | 4.8mil | 3.5mil | 4mil | 80 ohm | THICKNESS=1.2mm | 4.4/3.7 | 4.3/4.1 | 3.5/3.6 | 4.8/4.3 | 85 ohm | 4/4.1 | 3.5/4.3 | 88 ohm | 4/5 | 3.5/4.9 | 4.8/5.9 | 90 ohm | 4/5.7 | 100 ohm | 3.5/8.3 | 4/7 | (no ref) | 9/4.5 | L10-BOT | L1-TOP | L2-GND1 | L3-IN1 | L4-VCC | L5-IN2 | L6-IN3 | L7-GND2 | L8-IN4 | L9-GND3 | SB_1_2MM_10L(4MIL 50OHM)_WITHOUTC_151106
User.38: FIGURE | SIZE | 8.0 | 22.0 | 28.0 | 35.0 | 91.0 | 118.0 | 126.0 | 130.0 | 146.0 | 157.0 | 276.0 | 43.0 | 63.0 | 220.0 | 51.0x28.0 | 55.0x24.0 | 63.0x24.0 | 63.0x31.0 | 67.0x28.0 | 75.0x28.0 | 83.0x31.0 | 94.0x43.0 | 102.0x31.0 | 130.0x118.0 | 33.0x28.0 | 138.0x118.0 | DRILL CHART: TOP to BOTTOM | ALL UNITS ARE IN MILS | TOLERANCE | +3.0/-3.0 | +4.0/-4.0 | +2.0/-2.0 | PLATED | NON-PLATED | QTY | 9262 | 19 | 18 | 8 | 1 | 9 | 7 | 4 | 2
User.39: stack-up setting ok
